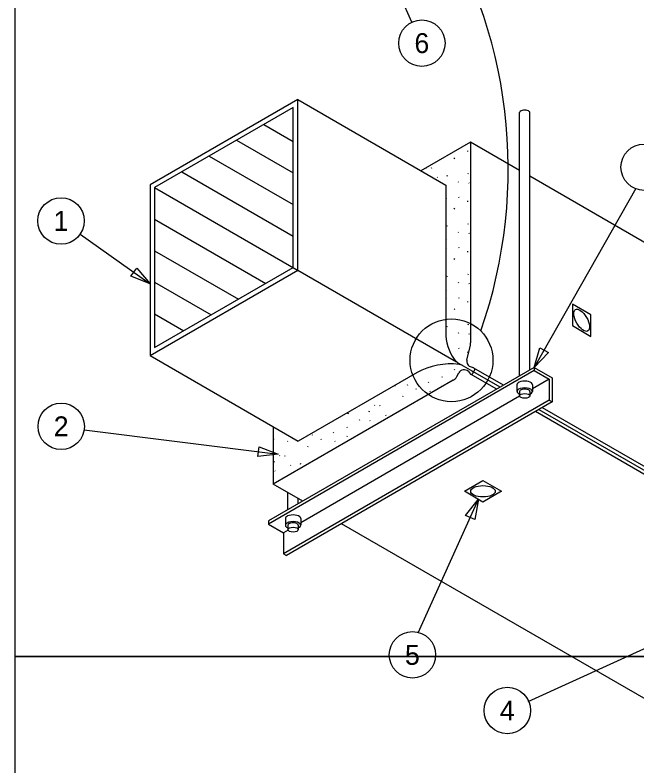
# Model space of a CAD drawing. Extents: x 10110.2 to 10159.4, y 10049.5 to 10140.5.
# Drawn here: x 10110.22 to 10131.09, y 10091.33 to 10116.52 of the extents above; entities that cross this region are included whole.
import ezdxf

# ---------------------------------------------------------------- set-up
doc = ezdxf.new("R2010")
doc.units = 0
for name, color, linetype in [('G-ANNO-SYMB', 7, 'Continuous'), ('G-DETL-GRID', 7, 'Continuous'), ('G-DETL-LINE', 7, 'Continuous'), ('G-DETL-TEXT', 7, 'Continuous')]:
    doc.layers.add(name, color=color, linetype=linetype)

msp = doc.modelspace()

# ---------------------------------------------------------------- linework, layer by layer
at = {"layer": 'G-ANNO-SYMB'}
for centre in [(10123.875, 10115.582), (10131.334, 10111.419), (10111.764, 10109.617), (10111.771, 10102.727), (10123.557, 10095.061), (10126.742, 10093.196)]:
    msp.add_circle(centre, 0.779, dxfattribs=at)
at = {"layer": 'G-DETL-GRID'}
for points in [[(10110.22, 10140.505), (10159.362, 10140.505), (10159.362, 10095.005), (10110.22, 10095.005)], [(10110.22, 10095.005), (10159.362, 10095.005), (10159.362, 10049.505), (10110.22, 10049.505)]]:
    msp.add_lwpolyline(points, close=True, dxfattribs=at)
at = {"layer": 'G-DETL-LINE'}
for p, q in [((10119.709, 10113.687), (10124.677, 10110.819)), ((10119.709, 10113.687), (10124.677, 10110.819)), ((10127.152, 10104.416), (10127.152, 10113.254)), ((10127.152, 10104.416), (10127.152, 10113.254)), ((10127.497, 10104.615), (10127.497, 10113.254)), ((10118.573, 10112.851), (10119.552, 10112.286)), ((10117.656, 10112.322), (10119.552, 10111.227)), ((10125.511, 10112.262), (10123.844, 10111.3)), ((10125.511, 10112.262), (10123.844, 10111.3)), ((10125.511, 10112.262), (10125.511, 10105.534)), ((10127.152, 10111.314), (10125.511, 10112.262)), ((10125.511, 10112.262), (10125.511, 10105.534)), ((10127.152, 10111.314), (10125.511, 10112.262)), ((10125.403, 10111.974), (10125.406, 10111.947)), ((10125.403, 10111.974), (10125.406, 10111.947)), ((10116.74, 10111.793), (10119.552, 10110.169)), ((10124.963, 10111.702), (10124.975, 10111.729)), ((10124.963, 10111.702), (10124.975, 10111.729)), ((10124.022, 10111.402), (10124.025, 10111.397)), ((10124.022, 10111.402), (10124.025, 10111.397)), ((10124.184, 10111.408), (10124.196, 10111.39)), ((10124.184, 10111.408), (10124.196, 10111.39)), ((10115.823, 10111.264), (10119.552, 10109.11)), ((10124.72, 10111.124), (10124.732, 10111.151)), ((10124.72, 10111.124), (10124.732, 10111.151)), ((10125.43, 10111.193), (10125.442, 10111.22)), ((10125.43, 10111.193), (10125.442, 10111.22)), ((10133.865, 10107.438), (10127.497, 10111.115)), ((10133.865, 10107.438), (10127.497, 10111.115)), ((10124.385, 10111.089), (10124.397, 10111.071)), ((10124.385, 10111.089), (10124.397, 10111.071)), ((10125.095, 10110.932), (10125.107, 10110.914)), ((10125.095, 10110.932), (10125.107, 10110.914)), ((10125.449, 10110.9), (10125.461, 10110.882)), ((10125.449, 10110.9), (10125.461, 10110.882)), ((10114.906, 10110.734), (10119.719, 10107.956)), ((10124.677, 10110.819), (10124.677, 10105.886)), ((10124.677, 10110.819), (10124.677, 10105.886)), ((10124.68, 10110.687), (10124.692, 10110.669)), ((10124.68, 10110.687), (10124.692, 10110.669)), ((10124.69, 10110.363), (10124.702, 10110.39)), ((10124.69, 10110.363), (10124.702, 10110.39)), ((10125.106, 10110.421), (10125.118, 10110.403)), ((10125.106, 10110.421), (10125.118, 10110.403)), ((10125.403, 10110.288), (10125.406, 10110.261)), ((10125.403, 10110.288), (10125.406, 10110.261)), ((10124.963, 10110.015), (10124.975, 10110.042)), ((10124.963, 10110.015), (10124.975, 10110.042)), ((10114.906, 10109.676), (10118.636, 10107.523)), ((10124.72, 10109.438), (10124.732, 10109.465)), ((10124.72, 10109.438), (10124.732, 10109.465)), ((10125.43, 10109.507), (10125.442, 10109.534)), ((10125.43, 10109.507), (10125.442, 10109.534)), ((10125.095, 10109.246), (10125.107, 10109.228)), ((10125.095, 10109.246), (10125.107, 10109.228)), ((10125.449, 10109.214), (10125.461, 10109.196)), ((10125.449, 10109.214), (10125.461, 10109.196)), ((10124.68, 10109.001), (10124.692, 10108.983)), ((10124.68, 10109.001), (10124.692, 10108.983)), ((10114.906, 10108.617), (10117.719, 10106.993)), ((10124.69, 10108.677), (10124.702, 10108.704)), ((10124.69, 10108.677), (10124.702, 10108.704)), ((10125.106, 10108.735), (10125.118, 10108.717)), ((10125.106, 10108.735), (10125.118, 10108.717)), ((10125.403, 10108.601), (10125.406, 10108.574)), ((10125.403, 10108.601), (10125.406, 10108.574)), ((10124.963, 10108.329), (10124.975, 10108.356)), ((10124.963, 10108.329), (10124.975, 10108.356)), ((10119.709, 10107.962), (10125.035, 10104.887)), ((10119.709, 10107.962), (10125.035, 10104.887)), ((10125.43, 10107.82), (10125.442, 10107.847)), ((10125.43, 10107.82), (10125.442, 10107.847)), ((10124.72, 10107.752), (10124.732, 10107.779)), ((10124.72, 10107.752), (10124.732, 10107.779)), ((10114.906, 10107.559), (10116.802, 10106.464)), ((10124.68, 10107.314), (10124.692, 10107.296)), ((10124.68, 10107.314), (10124.692, 10107.296)), ((10125.095, 10107.56), (10125.107, 10107.542)), ((10125.095, 10107.56), (10125.107, 10107.542)), ((10125.449, 10107.527), (10125.461, 10107.509)), ((10125.449, 10107.527), (10125.461, 10107.509)), ((10124.69, 10106.99), (10124.702, 10107.017)), ((10124.69, 10106.99), (10124.702, 10107.017)), ((10125.106, 10107.048), (10125.118, 10107.03)), ((10125.106, 10107.048), (10125.118, 10107.03)), ((10125.403, 10106.915), (10125.406, 10106.888)), ((10125.403, 10106.915), (10125.406, 10106.888)), ((10124.963, 10106.643), (10124.975, 10106.67)), ((10124.963, 10106.643), (10124.975, 10106.67)), ((10114.906, 10106.5), (10115.886, 10105.935)), ((10124.72, 10106.065), (10124.732, 10106.092)), ((10124.72, 10106.065), (10124.732, 10106.092)), ((10125.43, 10106.134), (10125.442, 10106.161)), ((10125.43, 10106.134), (10125.442, 10106.161)), ((10125.095, 10105.873), (10125.107, 10105.855)), ((10125.095, 10105.873), (10125.107, 10105.855)), ((10125.449, 10105.841), (10125.461, 10105.823)), ((10125.449, 10105.841), (10125.461, 10105.823)), ((10125.106, 10105.362), (10125.118, 10105.344)), ((10125.106, 10105.362), (10125.118, 10105.344)), ((10125.38, 10104.952), (10125.496, 10105.411)), ((10125.38, 10104.952), (10125.496, 10105.411)), ((10114.75, 10105.099), (10119.719, 10102.23)), ((10114.75, 10105.099), (10119.719, 10102.23)), ((10125.403, 10105.229), (10125.406, 10105.202)), ((10125.403, 10105.229), (10125.406, 10105.202)), ((10125.511, 10104.612), (10125.119, 10104.838)), ((10125.511, 10104.612), (10125.119, 10104.838)), ((10127.648, 10104.703), (10118.728, 10099.553)), ((10127.648, 10104.703), (10118.728, 10099.553)), ((10127.648, 10104.599), (10118.728, 10099.449)), ((10127.648, 10104.599), (10118.728, 10099.449)), ((10124.961, 10104.643), (10124.973, 10104.625)), ((10124.961, 10104.643), (10124.973, 10104.625)), ((10125.434, 10104.568), (10125.508, 10104.481)), ((10125.434, 10104.568), (10125.508, 10104.481)), ((10125.605, 10104.687), (10125.472, 10104.739)), ((10125.605, 10104.687), (10125.472, 10104.739)), ((10126.501, 10104.04), (10125.511, 10104.612)), ((10126.501, 10104.04), (10125.511, 10104.612)), ((10125.622, 10104.68), (10125.6, 10104.69)), ((10125.622, 10104.68), (10125.6, 10104.69)), ((10126.615, 10104.106), (10125.622, 10104.68)), ((10126.615, 10104.106), (10125.622, 10104.68)), ((10127.648, 10104.703), (10128.252, 10104.354)), ((10127.648, 10104.703), (10127.648, 10104.599)), ((10127.648, 10104.703), (10128.252, 10104.354)), ((10127.648, 10104.703), (10127.648, 10104.599)), ((10127.648, 10104.599), (10128.148, 10104.31)), ((10127.648, 10104.599), (10128.148, 10104.31)), ((10123.712, 10104.536), (10119.719, 10102.23)), ((10123.712, 10104.536), (10119.719, 10102.23)), ((10124.546, 10104.398), (10124.558, 10104.38)), ((10124.546, 10104.398), (10124.558, 10104.38)), ((10125.044, 10104.396), (10125.114, 10104.519)), ((10125.044, 10104.396), (10125.114, 10104.519)), ((10126.386, 10103.974), (10125.508, 10104.481)), ((10126.386, 10103.974), (10125.508, 10104.481)), ((10128.148, 10104.31), (10127.583, 10103.984)), ((10128.148, 10104.31), (10127.583, 10103.984)), ((10128.148, 10104.31), (10128.148, 10103.604)), ((10128.148, 10104.31), (10128.148, 10103.604)), ((10128.252, 10104.354), (10128.252, 10103.544)), ((10128.252, 10104.354), (10128.252, 10103.544)), ((10124.921, 10104.271), (10118.886, 10100.787)), ((10124.921, 10104.271), (10118.886, 10100.787)), ((10122.962, 10104.074), (10122.974, 10104.101)), ((10122.962, 10104.074), (10122.974, 10104.101)), ((10123.378, 10104.132), (10123.39, 10104.114)), ((10123.378, 10104.132), (10123.39, 10104.114)), ((10124.101, 10104.197), (10124.113, 10104.224)), ((10124.101, 10104.197), (10124.113, 10104.224)), ((10124.556, 10104.074), (10124.568, 10104.101)), ((10124.556, 10104.074), (10124.568, 10104.101)), ((10127.066, 10104.123), (10127.066, 10103.898)), ((10127.066, 10104.123), (10127.066, 10103.898)), ((10127.583, 10104.123), (10127.583, 10103.898)), ((10127.583, 10104.123), (10127.583, 10103.898)), ((10123.674, 10103.999), (10123.677, 10103.972)), ((10123.674, 10103.999), (10123.677, 10103.972)), ((10124.144, 10103.919), (10124.156, 10103.901)), ((10124.144, 10103.919), (10124.156, 10103.901)), ((10127.152, 10103.898), (10127.152, 10103.748)), ((10127.152, 10103.898), (10127.152, 10103.748)), ((10127.497, 10103.898), (10127.497, 10103.748)), ((10127.497, 10103.898), (10127.497, 10103.748)), ((10128.148, 10103.604), (10119.228, 10098.454)), ((10128.148, 10103.604), (10119.228, 10098.454)), ((10128.252, 10103.544), (10119.332, 10098.394)), ((10128.252, 10103.544), (10119.332, 10098.394)), ((10127.154, 10103.736), (10119.811, 10099.496)), ((10127.154, 10103.736), (10119.811, 10099.496)), ((10123.234, 10103.726), (10123.246, 10103.753)), ((10123.234, 10103.726), (10123.246, 10103.753)), ((10128.148, 10103.604), (10128.252, 10103.544)), ((10128.148, 10103.604), (10128.252, 10103.544)), ((10122.285, 10103.44), (10122.297, 10103.422)), ((10122.285, 10103.44), (10122.297, 10103.422)), ((10122.455, 10103.433), (10122.467, 10103.415)), ((10122.455, 10103.433), (10122.467, 10103.415)), ((10140.435, 10095.995), (10127.807, 10103.286)), ((10140.435, 10095.995), (10127.807, 10103.286)), ((10140.493, 10096.095), (10127.921, 10103.353)), ((10140.493, 10096.095), (10127.921, 10103.353)), ((10121.397, 10103.149), (10121.409, 10103.176)), ((10121.397, 10103.149), (10121.409, 10103.176)), ((10122.108, 10103.218), (10122.12, 10103.245)), ((10122.108, 10103.218), (10122.12, 10103.245)), ((10122.656, 10103.114), (10122.668, 10103.096)), ((10122.656, 10103.114), (10122.668, 10103.096)), ((10122.997, 10103.161), (10123.004, 10103.176)), ((10122.997, 10103.161), (10123.004, 10103.176)), ((10140.378, 10095.896), (10127.692, 10103.22)), ((10140.378, 10095.896), (10127.692, 10103.22)), ((10121.772, 10102.957), (10121.784, 10102.939)), ((10121.772, 10102.957), (10121.784, 10102.939)), ((10122.126, 10102.925), (10122.138, 10102.907)), ((10122.126, 10102.925), (10122.138, 10102.907)), ((10118.886, 10102.711), (10118.886, 10100.787)), ((10118.886, 10102.711), (10118.886, 10100.787)), ((10120.912, 10102.51), (10120.924, 10102.537)), ((10120.912, 10102.51), (10120.924, 10102.537)), ((10121.358, 10102.712), (10121.37, 10102.694)), ((10121.358, 10102.712), (10121.37, 10102.694)), ((10118.891, 10102.312), (10118.894, 10102.285)), ((10118.891, 10102.312), (10118.894, 10102.285)), ((10120.189, 10102.446), (10120.201, 10102.428)), ((10120.189, 10102.446), (10120.201, 10102.428)), ((10120.486, 10102.312), (10120.489, 10102.285)), ((10120.486, 10102.312), (10120.489, 10102.285)), ((10121.367, 10102.388), (10121.379, 10102.414)), ((10121.367, 10102.388), (10121.379, 10102.414)), ((10119.361, 10102.233), (10119.373, 10102.215)), ((10119.361, 10102.233), (10119.373, 10102.215)), ((10120.046, 10102.04), (10120.058, 10102.067)), ((10120.046, 10102.04), (10120.058, 10102.067)), ((10120.955, 10102.233), (10120.967, 10102.215)), ((10120.955, 10102.233), (10120.967, 10102.215)), ((10118.919, 10101.531), (10118.931, 10101.558)), ((10118.919, 10101.531), (10118.931, 10101.558)), ((10119.096, 10101.754), (10119.108, 10101.736)), ((10119.096, 10101.754), (10119.108, 10101.736)), ((10119.267, 10101.747), (10119.279, 10101.729)), ((10119.267, 10101.747), (10119.279, 10101.729)), ((10119.468, 10101.427), (10119.48, 10101.409)), ((10119.468, 10101.427), (10119.48, 10101.409)), ((10119.803, 10101.462), (10119.815, 10101.489)), ((10119.803, 10101.462), (10119.815, 10101.489)), ((10118.938, 10101.238), (10118.95, 10101.22)), ((10118.938, 10101.238), (10118.95, 10101.22)), ((10119.876, 10100.215), (10118.886, 10100.787)), ((10119.876, 10100.215), (10118.886, 10100.787)), ((10119.38, 10099.929), (10119.38, 10100.502)), ((10119.38, 10099.929), (10119.38, 10100.502)), ((10119.725, 10100.128), (10119.725, 10100.303)), ((10119.725, 10100.128), (10119.725, 10100.303)), ((10118.728, 10099.553), (10118.728, 10099.449)), ((10118.728, 10099.553), (10118.728, 10099.449)), ((10118.728, 10099.553), (10118.728, 10099.449)), ((10118.728, 10099.553), (10118.728, 10099.449)), ((10119.293, 10099.636), (10119.293, 10099.411)), ((10119.293, 10099.636), (10119.293, 10099.411)), ((10119.811, 10099.636), (10119.811, 10099.411)), ((10119.811, 10099.636), (10119.811, 10099.411)), ((10118.728, 10099.449), (10119.228, 10099.16)), ((10118.728, 10099.449), (10119.228, 10099.16)), ((10119.38, 10099.411), (10119.38, 10099.261)), ((10119.38, 10099.411), (10119.38, 10099.261)), ((10119.725, 10099.411), (10119.725, 10099.261)), ((10119.725, 10099.411), (10119.725, 10099.261)), ((10133.792, 10092.181), (10121.181, 10099.461)), ((10133.792, 10092.181), (10121.181, 10099.461)), ((10119.382, 10099.248), (10119.228, 10099.16)), ((10119.382, 10099.248), (10119.228, 10099.16)), ((10119.382, 10099.248), (10119.228, 10099.16)), ((10119.382, 10099.248), (10119.228, 10099.16)), ((10119.228, 10099.16), (10119.228, 10098.454)), ((10119.228, 10099.16), (10119.228, 10098.454)), ((10119.228, 10098.454), (10119.333, 10098.394)), ((10119.228, 10098.454), (10119.333, 10098.394))]:
    msp.add_line(p, q, dxfattribs=at)
for points in [[(10114.75, 10110.825), (10114.75, 10105.099), (10119.709, 10107.962), (10119.709, 10113.687)], [(10114.75, 10110.825), (10114.75, 10105.099), (10119.709, 10107.962), (10119.709, 10113.687)], [(10114.906, 10110.734), (10114.906, 10105.37), (10119.552, 10108.052), (10119.552, 10113.417)], [(10114.906, 10110.734), (10114.906, 10105.37), (10119.552, 10108.052), (10119.552, 10113.417)], [(10128.926, 10106.824), (10128.926, 10106.106), (10129.549, 10105.746), (10129.549, 10106.465)], [(10128.926, 10106.824), (10128.926, 10106.106), (10129.549, 10105.746), (10129.549, 10106.465)], [(10125.304, 10100.548), (10125.925, 10100.906), (10126.546, 10100.548), (10125.925, 10100.189)], [(10125.304, 10100.548), (10125.925, 10100.906), (10126.546, 10100.548), (10125.925, 10100.189)]]:
    msp.add_lwpolyline(points, close=True, dxfattribs=at)
for centre, radius, start, end in [((10126.201, 10105.867), 1.524, 179.2851, 215.6022), ((10126.201, 10105.867), 1.524, 179.2851, 215.6022), ((10125.011, 10105.534), 0.5, 345.8569, 0), ((10125.011, 10105.534), 0.5, 345.8569, 0), ((10124.843, 10102.442), 2.38, 83.3014, 118.3969), ((10124.843, 10102.442), 2.38, 83.3014, 118.3969), ((10125.369, 10105.271), 0.5, 215.6022, 240.0001), ((10125.369, 10105.271), 0.5, 215.6022, 240.0001), ((10125.082, 10104.475), 0.333, 60.0002, 83.3014), ((10125.082, 10104.475), 0.333, 60.0002, 83.3014), ((10125.604, 10104.923), 0.226, 172.6182, 234.4112), ((10125.604, 10104.923), 0.226, 172.6182, 234.4112), ((10125.293, 10104.416), 0.207, 47.0339, 150.7736), ((10125.293, 10104.416), 0.207, 47.0339, 150.7736), ((10125.536, 10104.531), 0.0573, 239.9993, 59.9993), ((10125.536, 10104.531), 0.0573, 239.9993, 59.9993), ((10125.593, 10104.63), 0.0573, 239.9993, 59.9993), ((10125.593, 10104.63), 0.0573, 239.9993, 59.9993), ((10124.754, 10104.56), 0.333, 300, 330.5386), ((10124.754, 10104.56), 0.333, 300, 330.5386)]:
    msp.add_arc(centre, radius, start, end, dxfattribs=at)
for centre, major_axis, start_param, end_param in [((10127.325, 10113.254), (-0.173, 0), 3.137491, 6.287287), ((10127.325, 10113.254), (-0.173, 0), 3.137491, 6.287287), ((10127.325, 10104.123), (-0.259, 0), 3.137491, 6.287287), ((10127.325, 10104.123), (-0.259, 0), 3.137491, 6.287287), ((10127.325, 10103.898), (-0.259, 0), 2.300516, 7.124262), ((10127.325, 10103.898), (-0.259, 0), 2.300516, 7.124262), ((10127.325, 10103.898), (-0.173, 0), 3.137491, 6.287287), ((10127.325, 10103.898), (-0.173, 0), 3.137491, 6.287287), ((10119.552, 10099.636), (-0.259, 0), 3.137491, 6.287287), ((10119.552, 10099.636), (-0.259, 0), 3.137491, 6.287287), ((10119.552, 10099.411), (-0.259, 0), 2.300516, 7.124262), ((10119.552, 10099.411), (-0.259, 0), 2.300516, 7.124262), ((10119.552, 10099.411), (-0.173, 0), 3.137491, 6.287287), ((10119.552, 10099.411), (-0.173, 0), 3.137491, 6.287287)]:
    msp.add_ellipse(centre, major_axis=major_axis, ratio=0.460797, start_param=start_param, end_param=end_param, dxfattribs=at)
for centre, major_axis, ratio in [((10129.237, 10106.285), (-0.207, 0.359), 0.461166), ((10129.237, 10106.285), (-0.207, 0.359), 0.461166), ((10127.325, 10103.748), (-0.173, 0), 0.460797), ((10127.325, 10103.748), (-0.173, 0), 0.460797), ((10125.925, 10100.548), (-0.413, 0), 0.460797), ((10125.925, 10100.548), (-0.413, 0), 0.460797), ((10119.552, 10099.261), (-0.173, 0), 0.460797), ((10119.552, 10099.261), (-0.173, 0), 0.460797)]:
    msp.add_ellipse(centre, major_axis=major_axis, ratio=ratio, dxfattribs=at)
at = {"layer": 'G-DETL-TEXT'}
for p, q in [((10123.54, 10116.28), (10121.64, 10120.551)), ((10131.056, 10110.703), (10127.648, 10104.703)), ((10131.056, 10110.703), (10127.648, 10104.703)), ((10112.408, 10109.176), (10114.75, 10107.512)), ((10112.546, 10102.615), (10119.053, 10101.796)), ((10112.546, 10102.615), (10119.053, 10101.796)), ((10123.744, 10095.797), (10125.769, 10100.279)), ((10123.744, 10095.797), (10125.769, 10100.279)), ((10127.445, 10093.492), (10133.067, 10096.065))]:
    msp.add_line(p, q, dxfattribs=at)
for points in [[(10114.303, 10108.034), (10114.75, 10107.512), (10114.11, 10107.762)], [(10114.303, 10108.034), (10114.75, 10107.512), (10114.11, 10107.762)], [(10128.122, 10105.2), (10127.648, 10104.703), (10127.833, 10105.365)], [(10128.122, 10105.2), (10127.648, 10104.703), (10127.833, 10105.365)], [(10118.413, 10102.045), (10119.053, 10101.796), (10118.371, 10101.714)], [(10118.413, 10102.045), (10119.053, 10101.796), (10118.371, 10101.714)], [(10125.343, 10099.74), (10125.769, 10100.279), (10125.647, 10099.603)], [(10125.343, 10099.74), (10125.769, 10100.279), (10125.647, 10099.603)]]:
    msp.add_lwpolyline(points, close=True, dxfattribs=at)
msp.add_circle((10124.868, 10104.944), 1.389, dxfattribs=at)
msp.add_arc((10110.325, 10111.351), 16.446, 340.7432, 32.9017, dxfattribs=at)

# ---------------------------------------------------------------- texts
at = {"layer": 'G-ANNO-SYMB'}
for s, p in [('6', (10123.625, 10115.249)), ('1', (10111.514, 10109.284)), ('2', (10111.521, 10102.394)), ('5', (10123.307, 10094.728)), ('4', (10126.492, 10092.863))]:
    msp.add_text(s, height=0.667, dxfattribs=at).set_placement(p)

doc.saveas('drawing.dxf')
